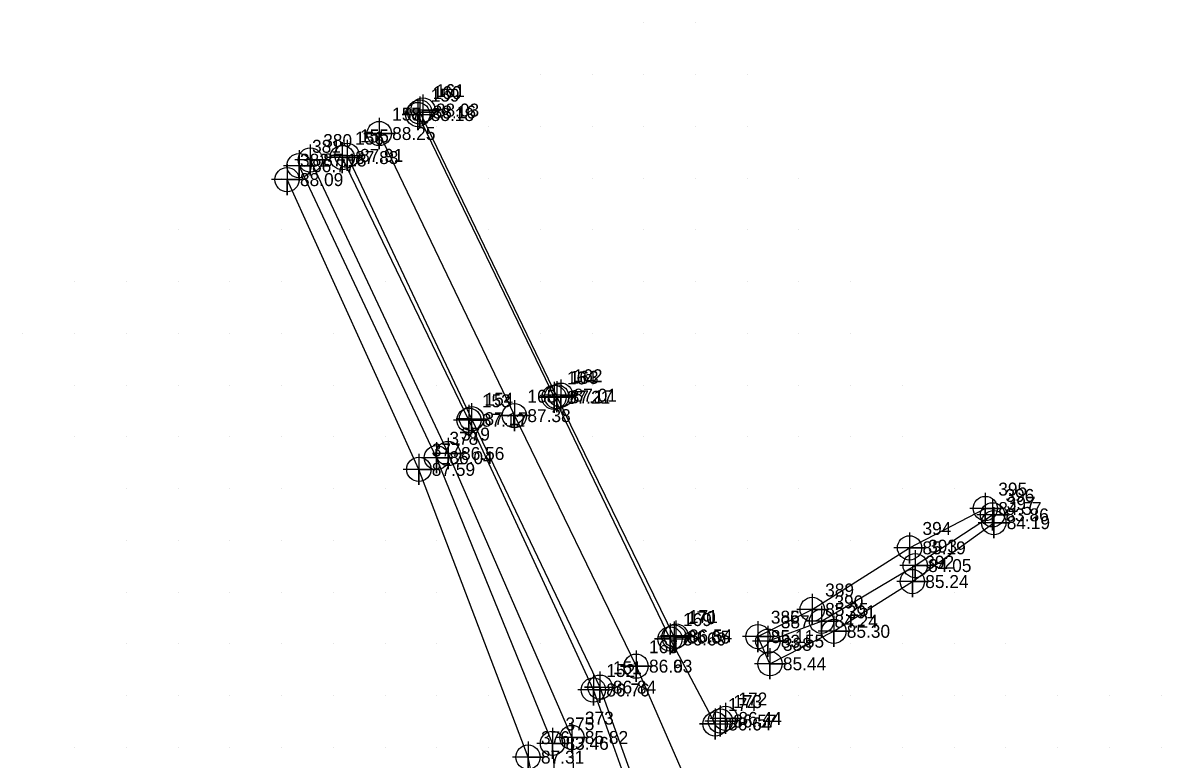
# Model space of a CAD drawing. Extents: x 1988140 to 1988766, y 249950 to 250250.
# Drawn here: x 1988150 to 1988370, y 250107.7 to 250250 of the extents above; entities that cross this region are included whole.
import ezdxf

# ---------------------------------------------------------------- set-up
doc = ezdxf.new("R2010")
doc.units = 0
for name, color, linetype in [('Exist DTM Breakline', 7, 'Continuous'), ('Exist DTM Breakline Cogo Elevation', 7, 'Continuous'), ('Exist DTM Breakline Cogo Number', 7, 'Continuous'), ('Exist DTM Breakline Cogo Point CELL', 7, 'Continuous'), ('Exist DTM Crownline', 7, 'Continuous'), ('Exist DTM Crownline Cogo Elevation', 7, 'Continuous'), ('Exist DTM Crownline Cogo Number', 7, 'Continuous'), ('Exist DTM Crownline Cogo Point CELL', 7, 'Continuous'), ('Exist DTM QL2 LIDAR Elevation Point', 7, 'Continuous'), ('Exist DTM Regular Point CELL', 7, 'Continuous'), ('Exist DTM Regular Point Cogo Elevation', 7, 'Continuous'), ('Exist DTM Regular Point Cogo Number', 7, 'Continuous'), ('Exist Roads EOP', 7, 'Continuous'), ('Exist Roads EOP Cogo Elevation', 7, 'Continuous'), ('Exist Roads EOP Cogo Number', 7, 'Continuous'), ('Exist Roads EOP Cogo Point CELL', 7, 'Continuous'), ('Exist Roads EOT', 7, 'Continuous'), ('Exist Roads EOT Cogo Elevation', 7, 'Continuous'), ('Exist Roads EOT Cogo Number', 7, 'Continuous'), ('Exist Roads EOT Cogo Point CELL', 7, 'Continuous')]:
    doc.layers.add(name, color=color, linetype=linetype)

msp = doc.modelspace()

# ---------------------------------------------------------------- linework, layer by layer
at = {"layer": 'Exist DTM Breakline'}
for points in [[(1988219.8819, 250076.4392), (1988239.9643, 250079.6884), (1988253.8373, 250091.0619), (1988252.3677, 250110.8012), (1988229.9431, 250165.984), (1988203.3987, 250222.3896)], [(1988205.5595, 250223.4953), (1988232.1956, 250166.792), (1988256.1231, 250111.9343), (1988257.1237, 250089.3736), (1988240.5529, 250076.9489), (1988219.1842, 250073.2983), (1988218.3199, 250076.6342), (1988218.9736, 250079.0217)], [(1988218.9736, 250079.0217), (1988239.4939, 250082.6807), (1988250.9135, 250092.6542), (1988247.6427, 250108.1384), (1988226.5384, 250163.725), (1988201.0735, 250219.7038)], [(1988294.396, 250126.1739), (1988292.0633, 250131.4249), (1988302.5552, 250136.6724), (1988321.3581, 250148.5633), (1988336.0088, 250156.1676)], [(1988293.9865, 250130.5297), (1988304.3523, 250134.3919), (1988322.4555, 250145.1454), (1988337.3961, 250154.9431)], [(1988294.396, 250126.1739), (1988306.7342, 250132.4456), (1988321.9056, 250142.056), (1988337.6438, 250153.4309)]]:
    msp.add_lwpolyline(points, dxfattribs=at)
at = {"layer": 'Exist DTM Breakline Cogo Point CELL'}
for points in [[(1988205.5595, 250226.4953), (1988205.5595, 250220.4953), (1988205.5595, 250223.4953), (1988208.5595, 250223.4953), (1988202.5595, 250223.4953)], [(1988203.3987, 250225.3896), (1988203.3987, 250219.3896), (1988203.3987, 250222.3896), (1988206.3987, 250222.3896), (1988200.3987, 250222.3896)], [(1988201.0735, 250222.7038), (1988201.0735, 250216.7038), (1988201.0735, 250219.7038), (1988204.0735, 250219.7038), (1988198.0735, 250219.7038)], [(1988229.9431, 250168.984), (1988229.9431, 250162.984), (1988229.9431, 250165.984), (1988232.9431, 250165.984), (1988226.9431, 250165.984)], [(1988232.1956, 250169.792), (1988232.1956, 250163.792), (1988232.1956, 250166.792), (1988235.1956, 250166.792), (1988229.1956, 250166.792)], [(1988226.5384, 250166.725), (1988226.5384, 250160.725), (1988226.5384, 250163.725), (1988229.5384, 250163.725), (1988223.5384, 250163.725)], [(1988336.0088, 250159.1676), (1988336.0088, 250153.1676), (1988336.0088, 250156.1676), (1988339.0088, 250156.1676), (1988333.0088, 250156.1676)], [(1988337.3961, 250157.9431), (1988337.3961, 250151.9431), (1988337.3961, 250154.9431), (1988340.3961, 250154.9431), (1988334.3961, 250154.9431)], [(1988337.6438, 250156.4309), (1988337.6438, 250150.4309), (1988337.6438, 250153.4309), (1988340.6438, 250153.4309), (1988334.6438, 250153.4309)], [(1988321.3581, 250151.5633), (1988321.3581, 250145.5633), (1988321.3581, 250148.5633), (1988324.3581, 250148.5633), (1988318.3581, 250148.5633)], [(1988322.4555, 250148.1454), (1988322.4555, 250142.1454), (1988322.4555, 250145.1454), (1988325.4555, 250145.1454), (1988319.4555, 250145.1454)], [(1988321.9056, 250145.056), (1988321.9056, 250139.056), (1988321.9056, 250142.056), (1988324.9056, 250142.056), (1988318.9056, 250142.056)], [(1988302.5552, 250139.6724), (1988302.5552, 250133.6724), (1988302.5552, 250136.6724), (1988305.5552, 250136.6724), (1988299.5552, 250136.6724)], [(1988304.3523, 250137.3919), (1988304.3523, 250131.3919), (1988304.3523, 250134.3919), (1988307.3523, 250134.3919), (1988301.3523, 250134.3919)], [(1988292.0633, 250134.4249), (1988292.0633, 250128.4249), (1988292.0633, 250131.4249), (1988295.0633, 250131.4249), (1988289.0633, 250131.4249)], [(1988292.0633, 250134.4249), (1988292.0633, 250128.4249), (1988292.0633, 250131.4249), (1988295.0633, 250131.4249), (1988289.0633, 250131.4249)], [(1988293.9865, 250133.5297), (1988293.9865, 250127.5297), (1988293.9865, 250130.5297), (1988296.9865, 250130.5297), (1988290.9865, 250130.5297)], [(1988306.7342, 250135.4456), (1988306.7342, 250129.4456), (1988306.7342, 250132.4456), (1988309.7342, 250132.4456), (1988303.7342, 250132.4456)], [(1988294.396, 250129.1739), (1988294.396, 250123.1739), (1988294.396, 250126.1739), (1988297.396, 250126.1739), (1988291.396, 250126.1739)], [(1988252.3677, 250113.8012), (1988252.3677, 250107.8012), (1988252.3677, 250110.8012), (1988255.3677, 250110.8012), (1988249.3677, 250110.8012)], [(1988256.1231, 250114.9343), (1988256.1231, 250108.9343), (1988256.1231, 250111.9343), (1988259.1231, 250111.9343), (1988253.1231, 250111.9343)], [(1988247.6427, 250111.1384), (1988247.6427, 250105.1384), (1988247.6427, 250108.1384), (1988250.6427, 250108.1384), (1988244.6427, 250108.1384)]]:
    msp.add_lwpolyline(points, dxfattribs=at)
for centre in [(1988205.5595, 250223.4953), (1988203.3987, 250222.3896), (1988201.0735, 250219.7038), (1988232.1956, 250166.792), (1988229.9431, 250165.984), (1988226.5384, 250163.725), (1988336.0088, 250156.1676), (1988337.3961, 250154.9431), (1988337.6438, 250153.4309), (1988321.3581, 250148.5633), (1988322.4555, 250145.1454), (1988321.9056, 250142.056), (1988302.5552, 250136.6724), (1988304.3523, 250134.3919), (1988292.0633, 250131.4249), (1988292.0633, 250131.4249), (1988306.7342, 250132.4456), (1988293.9865, 250130.5297), (1988294.396, 250126.1739), (1988256.1231, 250111.9343), (1988252.3677, 250110.8012), (1988247.6427, 250108.1384)]:
    msp.add_circle(centre, 2.344, dxfattribs=at)
at = {"layer": 'Exist DTM Crownline'}
msp.add_lwpolyline([(1988218.8793, 250228.6049), (1988245.0113, 250174.1068), (1988268.5227, 250125.7119), (1988280.5459, 250098.297), (1988299.095, 250058.5693)], dxfattribs=at)
at = {"layer": 'Exist DTM Crownline Cogo Point CELL'}
for points in [[(1988218.8793, 250231.6049), (1988218.8793, 250225.6049), (1988218.8793, 250228.6049), (1988221.8793, 250228.6049), (1988215.8793, 250228.6049)], [(1988245.0113, 250177.1068), (1988245.0113, 250171.1068), (1988245.0113, 250174.1068), (1988248.0113, 250174.1068), (1988242.0113, 250174.1068)], [(1988268.5227, 250128.7119), (1988268.5227, 250122.7119), (1988268.5227, 250125.7119), (1988271.5227, 250125.7119), (1988265.5227, 250125.7119)]]:
    msp.add_lwpolyline(points, dxfattribs=at)
for centre in [(1988218.8793, 250228.6049), (1988245.0113, 250174.1068), (1988268.5227, 250125.7119)]:
    msp.add_circle(centre, 2.344, dxfattribs=at)
at = {"layer": 'Exist DTM QL2 LIDAR Elevation Point'}
for p, q in [((1988270, 250250), (1988270, 250250)), ((1988280, 250250), (1988280, 250250)), ((1988250, 250240), (1988250, 250240)), ((1988260, 250240), (1988260, 250240)), ((1988270, 250240), (1988270, 250240)), ((1988280, 250240), (1988280, 250240)), ((1988290, 250240), (1988290, 250240)), ((1988230, 250230), (1988230, 250230)), ((1988240, 250230), (1988240, 250230)), ((1988250, 250230), (1988250, 250230)), ((1988260, 250230), (1988260, 250230)), ((1988270, 250230), (1988270, 250230)), ((1988280, 250230), (1988280, 250230)), ((1988290, 250230), (1988290, 250230)), ((1988200, 250220), (1988200, 250220)), ((1988210, 250220), (1988210, 250220)), ((1988240, 250220), (1988240, 250220)), ((1988250, 250220), (1988250, 250220)), ((1988260, 250220), (1988260, 250220)), ((1988270, 250220), (1988270, 250220)), ((1988280, 250220), (1988280, 250220)), ((1988290, 250220), (1988290, 250220)), ((1988300, 250220), (1988300, 250220)), ((1988180, 250210), (1988180, 250210)), ((1988190, 250210), (1988190, 250210)), ((1988200, 250210), (1988200, 250210)), ((1988240, 250210), (1988240, 250210)), ((1988250, 250210), (1988250, 250210)), ((1988260, 250210), (1988260, 250210)), ((1988270, 250210), (1988270, 250210)), ((1988280, 250210), (1988280, 250210)), ((1988290, 250210), (1988290, 250210)), ((1988300, 250210), (1988300, 250210)), ((1988160, 250200), (1988160, 250200)), ((1988170, 250200), (1988170, 250200)), ((1988180, 250200), (1988180, 250200)), ((1988190, 250200), (1988190, 250200)), ((1988200, 250200), (1988200, 250200)), ((1988210, 250200), (1988210, 250200)), ((1988220, 250200), (1988220, 250200)), ((1988250, 250200), (1988250, 250200)), ((1988260, 250200), (1988260, 250200)), ((1988270, 250200), (1988270, 250200)), ((1988280, 250200), (1988280, 250200)), ((1988290, 250200), (1988290, 250200)), ((1988300, 250200), (1988300, 250200)), ((1988310, 250200), (1988310, 250200)), ((1988150, 250190), (1988150, 250190)), ((1988160, 250190), (1988160, 250190)), ((1988170, 250190), (1988170, 250190)), ((1988180, 250190), (1988180, 250190)), ((1988190, 250190), (1988190, 250190)), ((1988200, 250190), (1988200, 250190)), ((1988210, 250190), (1988210, 250190)), ((1988250, 250190), (1988250, 250190)), ((1988260, 250190), (1988260, 250190)), ((1988270, 250190), (1988270, 250190)), ((1988280, 250190), (1988280, 250190)), ((1988290, 250190), (1988290, 250190)), ((1988300, 250190), (1988300, 250190)), ((1988310, 250190), (1988310, 250190)), ((1988160, 250180), (1988160, 250180)), ((1988170, 250180), (1988170, 250180)), ((1988180, 250180), (1988180, 250180)), ((1988190, 250180), (1988190, 250180)), ((1988200, 250180), (1988200, 250180)), ((1988210, 250180), (1988210, 250180)), ((1988230, 250180), (1988230, 250180)), ((1988260, 250180), (1988260, 250180)), ((1988270, 250180), (1988270, 250180)), ((1988280, 250180), (1988280, 250180)), ((1988290, 250180), (1988290, 250180)), ((1988300, 250180), (1988300, 250180)), ((1988310, 250180), (1988310, 250180)), ((1988320, 250180), (1988320, 250180)), ((1988160, 250170), (1988160, 250170)), ((1988170, 250170), (1988170, 250170)), ((1988180, 250170), (1988180, 250170)), ((1988190, 250170), (1988190, 250170)), ((1988200, 250170), (1988200, 250170)), ((1988210, 250170), (1988210, 250170)), ((1988220, 250170), (1988220, 250170)), ((1988260, 250170), (1988260, 250170)), ((1988270, 250170), (1988270, 250170)), ((1988280, 250170), (1988280, 250170)), ((1988290, 250170), (1988290, 250170)), ((1988300, 250170), (1988300, 250170)), ((1988310, 250170), (1988310, 250170)), ((1988320, 250170), (1988320, 250170)), ((1988170, 250160), (1988170, 250160)), ((1988180, 250160), (1988180, 250160)), ((1988190, 250160), (1988190, 250160)), ((1988200, 250160), (1988200, 250160)), ((1988210, 250160), (1988210, 250160)), ((1988220, 250160), (1988220, 250160)), ((1988270, 250160), (1988270, 250160)), ((1988280, 250160), (1988280, 250160)), ((1988290, 250160), (1988290, 250160)), ((1988300, 250160), (1988300, 250160)), ((1988310, 250160), (1988310, 250160)), ((1988320, 250160), (1988320, 250160)), ((1988330, 250160), (1988330, 250160)), ((1988170, 250150), (1988170, 250150)), ((1988180, 250150), (1988180, 250150)), ((1988190, 250150), (1988190, 250150)), ((1988200, 250150), (1988200, 250150)), ((1988210, 250150), (1988210, 250150)), ((1988220, 250150), (1988220, 250150)), ((1988230, 250150), (1988230, 250150)), ((1988270, 250150), (1988270, 250150)), ((1988280, 250150), (1988280, 250150)), ((1988290, 250150), (1988290, 250150)), ((1988300, 250150), (1988300, 250150)), ((1988310, 250150), (1988310, 250150)), ((1988320, 250150), (1988320, 250150)), ((1988170, 250140), (1988170, 250140)), ((1988180, 250140), (1988180, 250140)), ((1988190, 250140), (1988190, 250140)), ((1988200, 250140), (1988200, 250140)), ((1988210, 250140), (1988210, 250140)), ((1988220, 250140), (1988220, 250140)), ((1988230, 250140), (1988230, 250140)), ((1988280, 250140), (1988280, 250140)), ((1988290, 250140), (1988290, 250140)), ((1988300, 250140), (1988300, 250140)), ((1988330, 250140), (1988330, 250140)), ((1988170, 250130), (1988170, 250130)), ((1988180, 250130), (1988180, 250130)), ((1988190, 250130), (1988190, 250130)), ((1988200, 250130), (1988200, 250130)), ((1988210, 250130), (1988210, 250130)), ((1988220, 250130), (1988220, 250130)), ((1988230, 250130), (1988230, 250130)), ((1988250, 250130), (1988250, 250130)), ((1988280, 250130), (1988280, 250130)), ((1988290, 250130), (1988290, 250130)), ((1988310, 250130), (1988310, 250130)), ((1988320, 250130), (1988320, 250130)), ((1988330, 250130), (1988330, 250130)), ((1988340, 250130), (1988340, 250130)), ((1988170, 250120), (1988170, 250120)), ((1988180, 250120), (1988180, 250120)), ((1988190, 250120), (1988190, 250120)), ((1988200, 250120), (1988200, 250120)), ((1988210, 250120), (1988210, 250120)), ((1988220, 250120), (1988220, 250120)), ((1988230, 250120), (1988230, 250120)), ((1988240, 250120), (1988240, 250120)), ((1988290, 250120), (1988290, 250120)), ((1988300, 250120), (1988300, 250120)), ((1988310, 250120), (1988310, 250120)), ((1988320, 250120), (1988320, 250120)), ((1988330, 250120), (1988330, 250120)), ((1988340, 250120), (1988340, 250120)), ((1988350, 250120), (1988350, 250120)), ((1988360, 250120), (1988360, 250120)), ((1988370, 250120), (1988370, 250120)), ((1988160, 250110), (1988160, 250110)), ((1988170, 250110), (1988170, 250110)), ((1988180, 250110), (1988180, 250110)), ((1988190, 250110), (1988190, 250110)), ((1988200, 250110), (1988200, 250110)), ((1988210, 250110), (1988210, 250110)), ((1988220, 250110), (1988220, 250110)), ((1988230, 250110), (1988230, 250110)), ((1988240, 250110), (1988240, 250110)), ((1988260, 250110), (1988260, 250110)), ((1988300, 250110), (1988300, 250110)), ((1988310, 250110), (1988310, 250110)), ((1988320, 250110), (1988320, 250110)), ((1988330, 250110), (1988330, 250110)), ((1988340, 250110), (1988340, 250110)), ((1988350, 250110), (1988350, 250110)), ((1988360, 250110), (1988360, 250110)), ((1988370, 250110), (1988370, 250110))]:
    msp.add_line(p, q, dxfattribs=at)
at = {"layer": 'Exist DTM Regular Point CELL'}
for points in [[(1988227.3239, 250236.1398), (1988227.3239, 250230.1398), (1988227.3239, 250233.1398), (1988230.3239, 250233.1398), (1988224.3239, 250233.1398)], [(1988253.947, 250181.0657), (1988253.947, 250175.0657), (1988253.947, 250178.0657), (1988256.947, 250178.0657), (1988250.947, 250178.0657)], [(1988276.214, 250134.5519), (1988276.214, 250128.5519), (1988276.214, 250131.5519), (1988279.214, 250131.5519), (1988273.214, 250131.5519)], [(1988285.7897, 250118.6165), (1988285.7897, 250112.6165), (1988285.7897, 250115.6165), (1988288.7897, 250115.6165), (1988282.7897, 250115.6165)]]:
    msp.add_lwpolyline(points, dxfattribs=at)
for centre in [(1988227.3239, 250233.1398), (1988253.947, 250178.0657), (1988276.214, 250131.5519), (1988285.7897, 250115.6165)]:
    msp.add_circle(centre, 2.344, dxfattribs=at)
at = {"layer": 'Exist Roads EOP'}
for points in [[(1988226.7144, 250232.7585), (1988253.1931, 250177.7564), (1988275.8518, 250131.3247)], [(1988267.05, 250102.2049), (1988260.261, 250121.1174), (1988236.2175, 250173.2246), (1988211.7209, 250223.9639)]]:
    msp.add_lwpolyline(points, dxfattribs=at)
at = {"layer": 'Exist Roads EOP Cogo Point CELL'}
for points in [[(1988226.7144, 250235.7585), (1988226.7144, 250229.7585), (1988226.7144, 250232.7585), (1988229.7144, 250232.7585), (1988223.7144, 250232.7585)], [(1988211.7209, 250226.9639), (1988211.7209, 250220.9639), (1988211.7209, 250223.9639), (1988214.7209, 250223.9639), (1988208.7209, 250223.9639)], [(1988253.1931, 250180.7564), (1988253.1931, 250174.7564), (1988253.1931, 250177.7564), (1988256.1931, 250177.7564), (1988250.1931, 250177.7564)], [(1988236.2175, 250176.2246), (1988236.2175, 250170.2246), (1988236.2175, 250173.2246), (1988239.2175, 250173.2246), (1988233.2175, 250173.2246)], [(1988275.8518, 250134.3247), (1988275.8518, 250128.3247), (1988275.8518, 250131.3247), (1988278.8518, 250131.3247), (1988272.8518, 250131.3247)], [(1988260.261, 250124.1174), (1988260.261, 250118.1174), (1988260.261, 250121.1174), (1988263.261, 250121.1174), (1988257.261, 250121.1174)], [(1988284.7804, 250118.1175), (1988284.7804, 250112.1175), (1988284.7804, 250115.1175), (1988287.7804, 250115.1175), (1988281.7804, 250115.1175)]]:
    msp.add_lwpolyline(points, dxfattribs=at)
for centre in [(1988226.7144, 250232.7585), (1988211.7209, 250223.9639), (1988253.1931, 250177.7564), (1988236.2175, 250173.2246), (1988275.8518, 250131.3247), (1988260.261, 250121.1174), (1988284.7804, 250115.1175)]:
    msp.add_circle(centre, 2.344, dxfattribs=at)
at = {"layer": 'Exist Roads EOT'}
for points in [[(1988226.3364, 250232.2727), (1988252.658, 250177.644)], [(1988212.6737, 250224.3863), (1988236.7216, 250173.5203), (1988261.5404, 250121.6566), (1988268.3223, 250102.6287)], [(1988283.7918, 250114.5458), (1988275.0796, 250130.9591), (1988252.658, 250177.644)]]:
    msp.add_lwpolyline(points, dxfattribs=at)
at = {"layer": 'Exist Roads EOT Cogo Point CELL'}
for points in [[(1988226.3364, 250235.2727), (1988226.3364, 250229.2727), (1988226.3364, 250232.2727), (1988223.3364, 250232.2727), (1988229.3364, 250232.2727)], [(1988218.8793, 250231.6049), (1988218.8793, 250225.6049), (1988218.8793, 250228.6049), (1988215.8793, 250228.6049), (1988221.8793, 250228.6049)], [(1988212.6737, 250227.3863), (1988212.6737, 250221.3863), (1988212.6737, 250224.3863), (1988209.6737, 250224.3863), (1988215.6737, 250224.3863)], [(1988252.658, 250180.644), (1988252.658, 250174.644), (1988252.658, 250177.644), (1988249.658, 250177.644), (1988255.658, 250177.644)], [(1988236.7216, 250176.5203), (1988236.7216, 250170.5203), (1988236.7216, 250173.5203), (1988233.7216, 250173.5203), (1988239.7216, 250173.5203)], [(1988245.0113, 250177.1068), (1988245.0113, 250171.1068), (1988245.0113, 250174.1068), (1988242.0113, 250174.1068), (1988248.0113, 250174.1068)], [(1988275.0796, 250133.9591), (1988275.0796, 250127.9591), (1988275.0796, 250130.9591), (1988272.0796, 250130.9591), (1988278.0796, 250130.9591)], [(1988268.5227, 250128.7119), (1988268.5227, 250122.7119), (1988268.5227, 250125.7119), (1988265.5227, 250125.7119), (1988271.5227, 250125.7119)], [(1988261.5404, 250124.6566), (1988261.5404, 250118.6566), (1988261.5404, 250121.6566), (1988258.5404, 250121.6566), (1988264.5404, 250121.6566)], [(1988283.7918, 250117.5458), (1988283.7918, 250111.5458), (1988283.7918, 250114.5458), (1988280.7918, 250114.5458), (1988286.7918, 250114.5458)]]:
    msp.add_lwpolyline(points, dxfattribs=at)
for centre in [(1988226.3364, 250232.2727), (1988218.8793, 250228.6049), (1988212.6737, 250224.3863), (1988252.658, 250177.644), (1988236.7216, 250173.5203), (1988245.0113, 250174.1068), (1988275.0796, 250130.9591), (1988268.5227, 250125.7119), (1988261.5404, 250121.6566), (1988283.7918, 250114.5458)]:
    msp.add_circle(centre, 2.344, dxfattribs=at)

# ---------------------------------------------------------------- texts
at = {"layer": 'Exist DTM Breakline Cogo Elevation'}
for s, p in [('86.77', (1988205.8987, 250221.1396)), ('87.18', (1988208.0595, 250222.2453)), ('88.09', (1988203.5735, 250218.4538)), ('86.04', (1988232.4431, 250164.734)), ('86.56', (1988234.6956, 250165.542)), ('87.59', (1988229.0384, 250162.475)), ('84.57', (1988338.5088, 250154.9176)), ('83.86', (1988339.8961, 250153.6931)), ('84.19', (1988340.1438, 250152.1809)), ('85.19', (1988323.8581, 250147.3133)), ('84.05', (1988324.9555, 250143.8954)), ('85.24', (1988324.4056, 250140.806)), ('85.25', (1988305.0552, 250135.4224)), ('84.24', (1988306.8523, 250133.1419)), ('85.30', (1988309.2342, 250131.1956)), ('85.11', (1988294.5633, 250130.1749)), ('85.11', (1988294.5633, 250130.1749)), ('83.55', (1988296.4865, 250129.2797)), ('85.44', (1988296.896, 250124.9239)), ('83.46', (1988254.8677, 250109.5512)), ('85.82', (1988258.6231, 250110.6843)), ('87.31', (1988250.1427, 250106.8884))]:
    msp.add_text(s, height=2.5, dxfattribs=at).set_placement(p)
at = {"layer": 'Exist DTM Breakline Cogo Number'}
for s, p in [('380', (1988208.0595, 250225.9953)), ('381', (1988205.8987, 250224.8896)), ('382', (1988203.5735, 250222.2038)), ('378', (1988232.4431, 250168.484)), ('379', (1988234.6956, 250169.292)), ('377', (1988229.0384, 250166.225)), ('395', (1988338.5088, 250158.6676)), ('396', (1988339.8961, 250157.4431)), ('397', (1988340.1438, 250155.9309)), ('394', (1988323.8581, 250151.0633)), ('393', (1988324.9555, 250147.6454)), ('392', (1988324.4056, 250144.556)), ('389', (1988305.0552, 250139.1724)), ('390', (1988306.8523, 250136.8919)), ('385', (1988294.5633, 250133.9249)), ('386', (1988294.5633, 250133.9249)), ('391', (1988309.2342, 250134.9456)), ('387', (1988296.4865, 250133.0297)), ('388', (1988296.896, 250128.6739)), ('375', (1988254.8677, 250113.3012)), ('373', (1988258.6231, 250114.4343)), ('376', (1988250.1427, 250110.6384))]:
    msp.add_text(s, height=2.5, dxfattribs=at).set_placement(p)
at = {"layer": 'Exist DTM Crownline Cogo Elevation'}
for s, p in [('88.25', (1988221.3793, 250227.3549)), ('87.38', (1988247.5113, 250172.8568)), ('86.63', (1988271.0227, 250124.4619))]:
    msp.add_text(s, height=2.5, dxfattribs=at).set_placement(p)
at = {"layer": 'Exist DTM Crownline Cogo Number'}
for s, p in [('158', (1988221.3793, 250231.1049)), ('166', (1988247.5113, 250176.6068)), ('167', (1988271.0227, 250128.2119))]:
    msp.add_text(s, height=2.5, dxfattribs=at).set_placement(p)
at = {"layer": 'Exist DTM Regular Point Cogo Elevation'}
for s, p in [('88.03', (1988229.8239, 250231.8898)), ('87.01', (1988256.447, 250176.8157)), ('86.54', (1988278.714, 250130.3019)), ('86.44', (1988288.2897, 250114.3665))]:
    msp.add_text(s, height=2.5, dxfattribs=at).set_placement(p)
at = {"layer": 'Exist DTM Regular Point Cogo Number'}
for s, p in [('161', (1988229.8239, 250235.6398)), ('162', (1988256.447, 250180.5657)), ('171', (1988278.714, 250134.0519)), ('172', (1988288.2897, 250118.1165))]:
    msp.add_text(s, height=2.5, dxfattribs=at).set_placement(p)
at = {"layer": 'Exist Roads EOP Cogo Elevation'}
for s, p in [('88.16', (1988229.2144, 250231.5085)), ('87.83', (1988214.2209, 250222.7139)), ('87.17', (1988255.6931, 250176.5064)), ('87.12', (1988238.7175, 250171.9746)), ('86.65', (1988278.3518, 250130.0747)), ('86.76', (1988262.761, 250119.8674)), ('86.57', (1988287.2804, 250113.8675))]:
    msp.add_text(s, height=2.5, dxfattribs=at).set_placement(p)
at = {"layer": 'Exist Roads EOP Cogo Number'}
for s, p in [('160', (1988229.2144, 250235.2585)), ('156', (1988214.2209, 250226.4639)), ('163', (1988255.6931, 250180.2564)), ('153', (1988238.7175, 250175.7246)), ('170', (1988278.3518, 250133.8247)), ('152', (1988262.761, 250123.6174)), ('173', (1988287.2804, 250117.6175))]:
    msp.add_text(s, height=2.5, dxfattribs=at).set_placement(p)
at = {"layer": 'Exist Roads EOT Cogo Elevation'}
for s, p in [('88.18', (1988228.8364, 250231.0227)), ('88.25', (1988221.3793, 250227.3549)), ('87.91', (1988215.1737, 250223.1363)), ('87.21', (1988255.158, 250176.394)), ('87.38', (1988247.5113, 250172.8568)), ('87.17', (1988239.2216, 250172.2703)), ('86.69', (1988277.5796, 250129.7091)), ('86.93', (1988271.0227, 250124.4619)), ('86.84', (1988264.0404, 250120.4066)), ('86.64', (1988286.2918, 250113.2958))]:
    msp.add_text(s, height=2.5, dxfattribs=at).set_placement(p)
at = {"layer": 'Exist Roads EOT Cogo Number'}
for s, p in [('159', (1988228.8364, 250234.7727)), ('157', (1988221.3793, 250231.1049)), ('155', (1988215.1737, 250226.8863)), ('164', (1988255.158, 250180.144)), ('154', (1988239.2216, 250176.0203)), ('165', (1988247.5113, 250176.6068)), ('169', (1988277.5796, 250133.4591)), ('168', (1988271.0227, 250128.2119)), ('151', (1988264.0404, 250124.1566)), ('174', (1988286.2918, 250117.0458))]:
    msp.add_text(s, height=2.5, dxfattribs=at).set_placement(p)

doc.saveas('drawing.dxf')
